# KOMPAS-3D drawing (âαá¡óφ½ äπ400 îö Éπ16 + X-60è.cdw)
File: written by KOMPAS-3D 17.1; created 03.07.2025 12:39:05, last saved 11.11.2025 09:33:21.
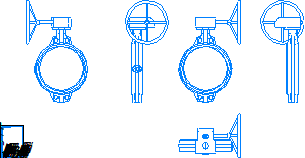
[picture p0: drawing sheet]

Sheet 1: A4, portrait

Title block, sheet 1: sheets: 1; sheet format: A4; stored path: \\adlc.lan\data\АДЛ_ПКД\3D-модели\ADL production\Дисковые поворотные затворы ГРАНВЭЛ\межфланцевый с китайским редуктором Ру16\KOMPAS 2D\Гранвэл Ду400 МФ Ру16 + X-60К.cdw

Views: Вид 1, Спереди, Проекционный вид 2, Проекционный вид 3, Проекционный вид 4, Проекционный вид 5
Referenced files in \\adlc.lan\data\АДЛ_ПКД\3D-модели\ADL production\Дисковые поворотные затворы ГРАНВЭЛ\межфланцевый с китайским редуктором Ру16\KOMPAS 3D\: Гранвэл Ду400 МФ Ру16 + X-60К.m3d
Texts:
  Andrey
  АДЛ
Dimensions and other numbers on the sheet: 1:1; 1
